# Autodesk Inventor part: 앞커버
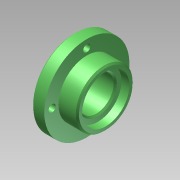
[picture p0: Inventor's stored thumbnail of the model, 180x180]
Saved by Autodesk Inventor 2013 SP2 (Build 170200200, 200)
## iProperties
Created: 2025-04
Part Number: 앞커버
Material: Generic
Document SubType Name: Modeling
Designer: i
Density: 1 g/cm^3
Author: i
변환 표준: STEP AP214IS
전처리기: Build: 200, Release: 2013 SP2 Update 6 - Date: Thu 07/17/2014
전송 단위: 밀리미터
불확실성: 0.01
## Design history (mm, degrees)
node "앞커버1"
node "솔리드1"
node "기준1"
